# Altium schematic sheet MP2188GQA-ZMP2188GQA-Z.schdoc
size 127 x 101 mm
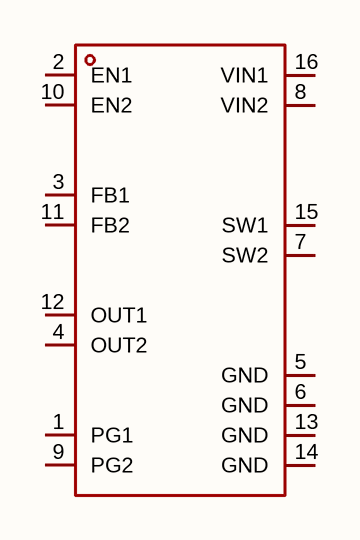
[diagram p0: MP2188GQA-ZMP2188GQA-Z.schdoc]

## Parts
U?  mp2188gqa-z  [QFN-16_L2.6-W2.2-P0.40_MP2188GQA]  (value not drawn)

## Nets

Not connected (* = marked no-connect by the designer): U? 1(PG1) 2(EN1) 3(FB1) 4(OUT2) 5(GND) 6(GND) 7(SW2) 8(VIN2) 9(PG2) 10(EN2) 11(FB2) 12(OUT1) 13(GND) 14(GND) 15(SW1) 16(VIN1)

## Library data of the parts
U? = mp2188gqa-z: 功能类型:降压型;工作电压:2.5V~5.5V;输出电压:800mV~5.5V;输出电流:3A;输出类型:可调;; Manufacturer: MPS(芯源); AddInBom: yes; ModelId: ec57a5bbca97494294e3097f31c4f782; ModelTransform: 87.4014,103.1494,0,0,0,0,0,0,0; Function: 降压型; Output Current: 3A; Frequency - Switching: 1.2MHz; Synchronous Rectifier: 是; Number of Outputs: 2; Topology: 降压式; Quiescent Current: 80uA; Switch tube (built-in/external): 内置; Output Type: 可调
